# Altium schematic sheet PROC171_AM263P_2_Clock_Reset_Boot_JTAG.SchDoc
size 431 x 279 mm; Date: Not shown in title block; ApprovedBy: Not shown in title block; CheckedBy: Not shown in title block; Author: Not shown in title block; CompanyName: Not shown in title block; Engineer: Srinivas; Organization: Not shown in title block; Address1: Not shown in title block; Address2: Not shown in title block; Address3: Not shown in title block; Address4: Not shown in title block; DocumentNumber: 5; Revision: Use project parameter SCH_Rev; SheetNumber: 5; SheetTotal: 26; PageSetup: Record=PageOptions¦CenterHorizontal=True¦CenterVertical=True¦PrintScale=1.00¦XCorrection=1.00¦YCorrection=1.00¦PrintKind=0¦BorderSize=5000000¦LeftOffset=0¦BottomOffset=0¦Orientation=2¦PaperLength=1000¦PaperWidth=1000¦Scale=100¦PaperSource=15¦PrintQuality=600¦MediaType=1¦DitherType=10¦PaperKind=Letter¦PrintScaleMode=1
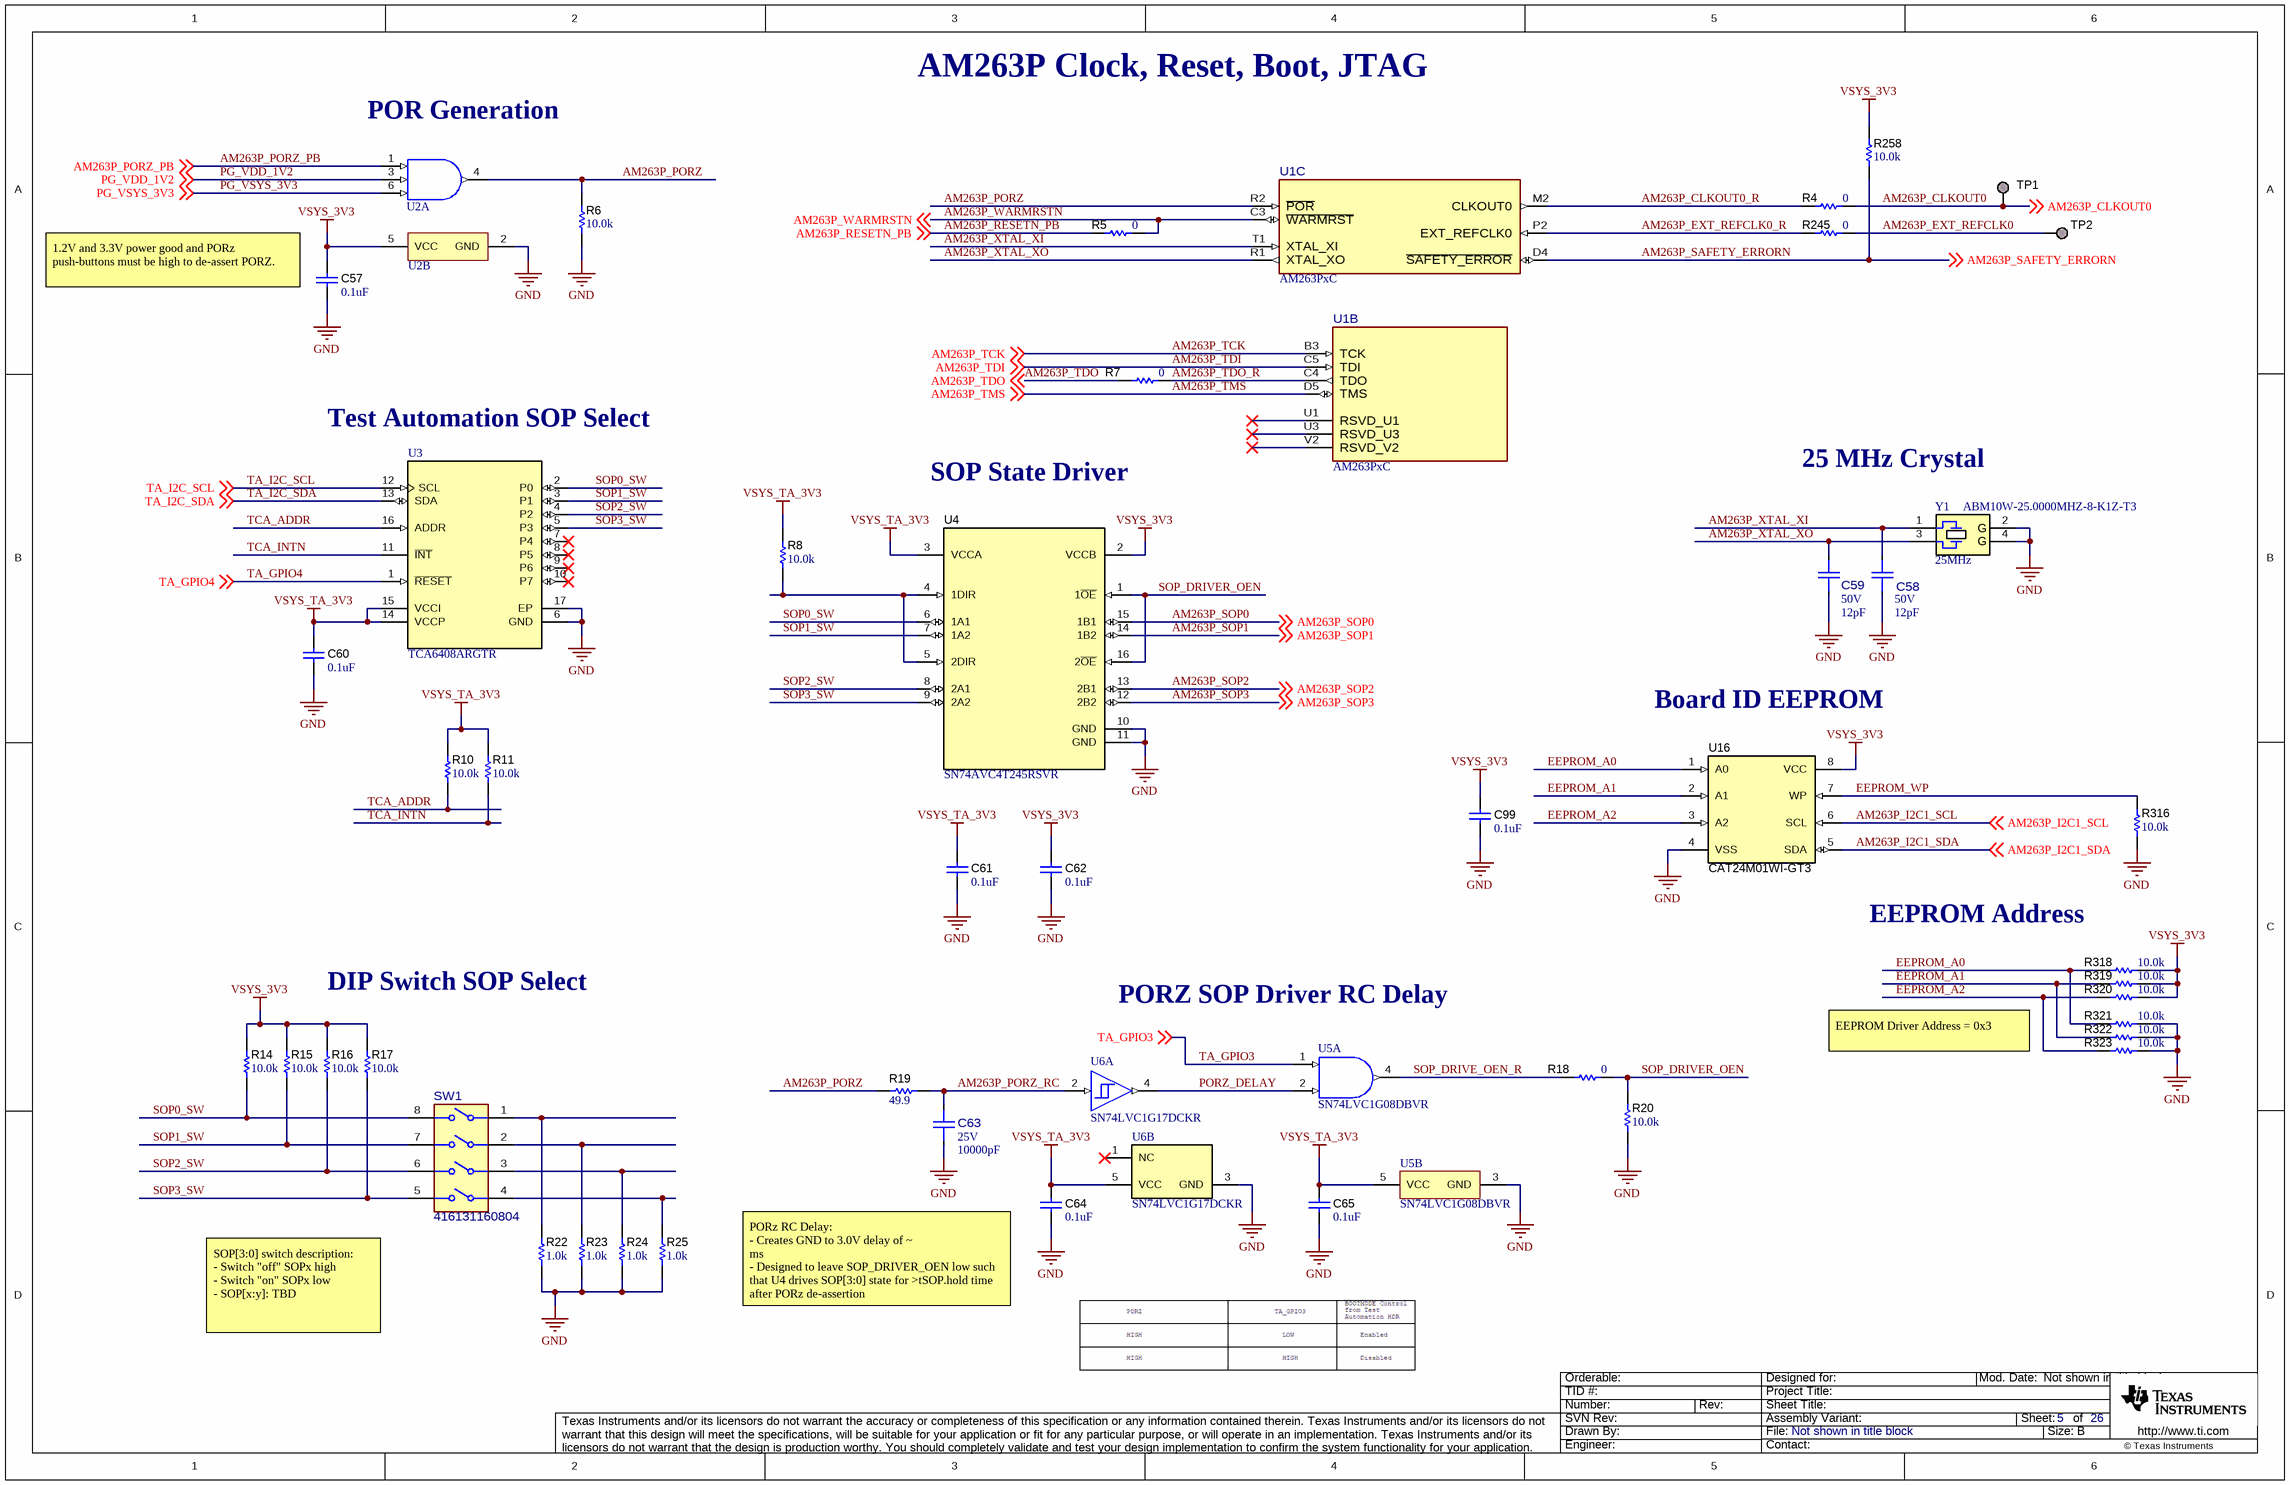
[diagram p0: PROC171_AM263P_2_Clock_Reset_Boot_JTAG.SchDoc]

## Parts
C57  ValueDisplayed: 0.1uF  [0402]  (hidden comment: GRM155R71E104KE14D)
C58  VDC_V: 50V  ValueDisplayed: 12pF  [FP-GJM1555C1H120JB01D_0402-MFG]  (hidden comment: GJM1555C1H120JB01D)
C59  VDC_V: 50V  ValueDisplayed: 12pF  [FP-GJM1555C1H120JB01D_0402-MFG]  (hidden comment: GJM1555C1H120JB01D)
C60  ValueDisplayed: 0.1uF  [0402]  (hidden comment: GRM155R71E104KE14D)
C61  ValueDisplayed: 0.1uF  [0402]  (hidden comment: GRM155R71E104KE14D)
C62  ValueDisplayed: 0.1uF  [0402]  (hidden comment: GRM155R71E104KE14D)
C63  VDC_V: 25V  ValueDisplayed: 10000pF  [FP-GRM1555C1E103JE01D_0402-MFG]  (hidden comment: GRM1555C1E103JE01D)
C64  ValueDisplayed: 0.1uF  [0402]  (hidden comment: GRM155R71E104KE14D)
C65  ValueDisplayed: 0.1uF  [0402]  (hidden comment: GRM155R71E104KE14D)
C99  ValueDisplayed: 0.1uF  [0402]  (hidden comment: GRM155R71E104KE14D)
R4  value 0  [0402L]  (hidden comment: ERJ-2GE0R00X)
R5  ValueDisplayed: 0  [0402]  (hidden comment: ERJ-2GE0R00X)
R6  ValueDisplayed: 10.0k  [0402]  (hidden comment: ERJ-2RKF1002X)
R7  value 0  [0402L]  (hidden comment: ERJ-2GE0R00X)
R8  ValueDisplayed: 10.0k  [0402]  (hidden comment: ERJ-2RKF1002X)
R10  ValueDisplayed: 10.0k  [0402]  (hidden comment: ERJ-2RKF1002X)
R11  ValueDisplayed: 10.0k  [0402]  (hidden comment: ERJ-2RKF1002X)
R14  ValueDisplayed: 10.0k  [0402]  (hidden comment: ERJ-2RKF1002X)
R15  ValueDisplayed: 10.0k  [0402]  (hidden comment: ERJ-2RKF1002X)
R16  ValueDisplayed: 10.0k  [0402]  (hidden comment: ERJ-2RKF1002X)
R17  ValueDisplayed: 10.0k  [0402]  (hidden comment: ERJ-2RKF1002X)
R18  ValueDisplayed: 0  [0402]  (hidden comment: ERJ-2GE0R00X)
R19  ValueDisplayed: 49.9  [0402]  (hidden comment: ERJ-2RKF49R9X)
R20  ValueDisplayed: 10.0k  [0402]  (hidden comment: ERJ-2RKF1002X)
R22  ValueDisplayed: 1.0k  [0402]  (hidden comment: ERJ-2GEJ102X)
R23  ValueDisplayed: 1.0k  [0402]  (hidden comment: ERJ-2GEJ102X)
R24  ValueDisplayed: 1.0k  [0402]  (hidden comment: ERJ-2GEJ102X)
R25  ValueDisplayed: 1.0k  [0402]  (hidden comment: ERJ-2GEJ102X)
R245  value 0  [0402L]  (hidden comment: ERJ-2GE0R00X)
R258  ValueDisplayed: 10.0k  [0402]  (hidden comment: ERJ-2RKF1002X)
R316  ValueDisplayed: 10.0k  [0402]  (hidden comment: ERJ-2RKF1002X)
R318  ValueDisplayed: 10.0k  [0402]  (hidden comment: ERJ-2RKF1002X)
R319  ValueDisplayed: 10.0k  [0402]  (hidden comment: ERJ-2RKF1002X)
R320  ValueDisplayed: 10.0k  [0402]  (hidden comment: ERJ-2RKF1002X)
R321  ValueDisplayed: 10.0k  [0402]  (hidden comment: ERJ-2RKF1002X)
R322  ValueDisplayed: 10.0k  [0402]  (hidden comment: ERJ-2RKF1002X)
R323  ValueDisplayed: 10.0k  [0402]  (hidden comment: ERJ-2RKF1002X)
SW1  416131160804  [FP-416131160804_SMT_SW-MFG]
TP1  TP_SM_1MM  [TP_SM_1MM]  (value not drawn)  (no BOM)
TP2  TP_SM_1MM  [TP_SM_1MM]  (value not drawn)  (no BOM)
U1  AM263PxC  [ZCZ0324A-MFG]  (parts B,C of 13)
U2  SN74LVC1G11DBVR  [DBV0006A_N]  (value not drawn)  (parts A,B of 2)
U3  TCA6408ARGTR  [RGT0016A]
U4  SN74AVC4T245RSVR  [RSV0016A]
U5  SN74LVC1G08DBVR  [DBV0005A_N]  (parts A,B of 2)
U6  SN74LVC1G17DCKR  [DCK0005A_N]  (parts A,B of 2)
U16  CAT24M01WI-GT3  [SOIC-8]
Y1  Frequency_Fixed: 25MHz  PartNumber: ABM10W-25.0000MHZ-8-K1Z-T3  [Abracon_ABM10W]  (hidden comment: ABM10W-25.0000MHZ-4-D1X-T3)

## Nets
GND: C57.1 C58.1 C59.1 C60.1 C61.1 C62.1 C63.1 C64.1 C65.1 C99.1 R6.1 R20.2 R22.1 R23.1 R24.1 R25.1 R316.2 R321.1 R322.1 R323.1 U2.2(GND) U3.6(GND) U3.17(EP) U4.10(GND) U4.11(GND) U5.3(GND) U6.3(GND) U16.4(VSS) Y1.2(GND) Y1.4(GND)
VSYS_3V3: C57.2 C62.2 C99.2 R14.1 R15.1 R16.1 R17.1 R258.2 R318.1 R319.1 R320.1 U2.5(VCC) U4.2(VCCB) U16.8(VCC)
VSYS_TA_3V3: C60.2 C61.2 C64.2 C65.2 R8.1 R10.1 R11.1 U3.14(VCCP) U3.15(VCCI) U4.3(VCCA) U5.5(VCC) U6.5(VCC)
AM263P_CLKOUT0: R4.2 TP1.1 ; off-sheet AM263P_CLKOUT0
AM263P_CLKOUT0_R: R4.1 U1.M2(CLKOUT0)
AM263P_EXT_REFCLK0: R245.2 TP2.1
AM263P_EXT_REFCLK0_R: R245.1 U1.P2(EXT_REFCLK0)
AM263P_I2C1_SCL: U16.6(SCL) ; off-sheet AM263P_I2C1_SCL
AM263P_I2C1_SDA: U16.5(SDA) ; off-sheet AM263P_I2C1_SDA
AM263P_PORZ: R6.2 R19.1 U1.R2(~{POR}) U2.4(Y)
AM263P_PORZ_PB: U2.1(A) ; off-sheet AM263P_PORZ_PB
AM263P_PORZ_RC: C63.2 R19.2 U6.2(A)
AM263P_RESETN_PB: R5.1 ; off-sheet AM263P_RESETN_PB
AM263P_SAFETY_ERRORN: R258.1 U1.D4(~{SAFETY_ERROR}) ; off-sheet AM263P_SAFETY_ERRORN
AM263P_SOP0: U4.15(1B1) ; off-sheet AM263P_SOP0
AM263P_SOP1: U4.14(1B2) ; off-sheet AM263P_SOP1
AM263P_SOP2: U4.13(2B1) ; off-sheet AM263P_SOP2
AM263P_SOP3: U4.12(2B2) ; off-sheet AM263P_SOP3
AM263P_TCK: U1.B3(TCK) ; off-sheet AM263P_TCK
AM263P_TDI: U1.C5(TDI) ; off-sheet AM263P_TDI
AM263P_TDO: R7.1 ; off-sheet AM263P_TDO
AM263P_TDO_R: R7.2 U1.C4(TDO)
AM263P_TMS: U1.D5(TMS) ; off-sheet AM263P_TMS
AM263P_WARMRSTN: R5.2 U1.C3(~{WARMRST}) ; off-sheet AM263P_WARMRSTN
AM263P_XTAL_XI: C58.2 U1.T1(XTAL_XI) Y1.1
AM263P_XTAL_XO: C59.2 U1.R1(XTAL_XO) Y1.3
EEPROM_A0: R318.2 R321.2 U16.1(A0)
EEPROM_A1: R319.2 R322.2 U16.2(A1)
EEPROM_A2: R320.2 R323.2 U16.3(A2)
EEPROM_WP: R316.1 U16.7(WP)
PG_VDD_1V2: U2.3(B) ; off-sheet PG_VDD_1V2
PG_VSYS_3V3: U2.6(C) ; off-sheet PG_VSYS_3V3
PORZ_DELAY: U5.2(B) U6.4(Y)
SOP0_SW: R14.2 SW1.8 U3.2(P0) U4.6(1A1)
SOP1_SW: R15.2 SW1.7 U3.3(P1) U4.7(1A2)
SOP2_SW: R16.2 SW1.6 U3.4(P2) U4.8(2A1)
SOP3_SW: R17.2 SW1.5 U3.5(P3) U4.9(2A2)
SOP_DRIVE_OEN_R: R18.1 U5.4(Y)
SOP_DRIVER_OEN: R18.2 R20.1 U4.1(1~{OE}) U4.16(2~{OE})
TA_GPIO3: U5.1(A) ; off-sheet TA_GPIO3
TA_GPIO4: U3.1(~{RESET}) ; off-sheet TA_GPIO4
TA_I2C_SCL: U3.12(SCL) ; off-sheet TA_I2C_SCL
TA_I2C_SDA: U3.13(SDA) ; off-sheet TA_I2C_SDA
TCA_ADDR: R10.2 U3.16(ADDR)
TCA_INTN: R11.2 U3.11(~{INT})
NetR8_2: R8.2 U4.4(1DIR) U4.5(2DIR)
NetR22_2: R22.2 SW1.1
NetR23_2: R23.2 SW1.2
NetR24_2: R24.2 SW1.3
NetR25_2: R25.2 SW1.4

Not connected (* = marked no-connect by the designer): U1 U1(RSVD_U1)* U3(RSVD_U3)* V2(RSVD_V2)*; U3 7(P4)* 8(P5)* 9(P6)* 10(P7)*; U6 1(NC)*

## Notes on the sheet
- AM263P Clock, Reset, Boot, JTAG
- (near U2) POR Generation
- (near C57) 1.2V and 3.3V power good and PORz push-buttons must be high to de-assert PORZ.
- Test Automation SOP Select
- SOP State Driver
- 25 MHz Crystal
- Board ID EEPROM
- EEPROM Address
- DIP Switch SOP Select
- PORZ SOP Driver RC Delay
- EEPROM Driver Address = 0x3
- (near C64) PORz RC Delay:
  - Creates GND to 3.0V delay of ~
  ms
  - Designed to leave SOP_DRIVER_OEN low such that U4 drives SOP[3:0] state for >tSOP.hold time after PORz de-assertion
- SOP[3:0] switch description:
  - Switch "off" SOPx high
  - Switch "on" SOPx low
  - SOP[x:y]: TBD

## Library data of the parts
C57 C60-C62 C64 C65 C99 = CMP-0006659-2: CAP, CERM, 0.1 uF, 25 V, +/- 10%, X7R, 0402; Manufacturer: MuRata; TaMin_C: -55°C; Polarized: N; SizeAreaWB_mm2: 3; U/M: EA; Value: 0.1uF; TaMax_C: 125°C; SizeZ_mm: 0.6; SizeX_mm: 1; SizeY_mm: 0.5; Value2: 25V; Cap_F: 100nF; AEC Category: Q200; Value1: Unknown
C58 C59 = CMP-0035228-1: Multi-Layer Ceramic Capacitor 12pF C0G  ±5% 0402 Paper T/R; Manufacturer: Murata; TempCo: 30ppm/°C; SizeZ_mm: 0.55mm; AEC Qualified: No
C63 = CMP-0035343-1: Chip Multilayer Ceramic Capacitors for General Purpose, 0402, 10000pF, C0G, 30ppm/°C, 5%, 25V; Manufacturer: Murata; Value: 10nF; SizeZ_mm: 0.65mm; AEC Qualified: No
R4 R7 R245 = CMP-0026992-3: RES, 0, 5%, 0.1 W, AEC-Q200 Grade 0, 0402; Manufacturer: Panasonic; Power_W: 100mW; TempCo: 600 ppm/C; Value_Code: 0000; EIA_Code: E24; SizeX_mm: 1; SizeY_mm: 0.5; SizeZ_mm: 0.6; Value2: 0.1W; AEC Qualified: Y; VDC_V: 50V; AEC Category: Q200; SizeAreaWB_mm2: 3
R5 R18 = CMP-0026992-3: RES, 0, 5%, 0.1 W, AEC-Q200 Grade 0, 0402; Manufacturer: Panasonic; Power_W: 100mW; TempCo: 600 ppm/C; Value_Code: 0000; Value: 0; EIA_Code: E24; SizeX_mm: 1; SizeY_mm: 0.5; SizeZ_mm: 0.6; Value2: 0.1W; AEC Qualified: Y; VDC_V: 50V; AEC Category: Q200; SizeAreaWB_mm2: 3
R6 R8 R10 R11 R14-R17 R20 R258 R316 R318-R323 = CMP-0026658-1: RES, 10.0 k, 1%, 0.1 W, 0402; Manufacturer: Panasonic; Power_W: 100mW; TempCo: 100 ppm/C; Value_Code: 10k0; U/M: EA; Value: 10.0k; EIA_Code: E96; Res_ohm: 10k; SizeX_mm: 1; SizeY_mm: 0.5; SizeZ_mm: 0.6; Value2: 0.1W; VDC_V: 50V; AEC Category: Q200
R19 = CMP-0026703-1: RES, 49.9, 1%, 0.1 W, AEC-Q200 Grade 0, 0402; Manufacturer: Panasonic; Power_W: 100mW; TempCo: 100 ppm/C; Value_Code: 49R9; U/M: EA; Value: 49.9; EIA_Code: E96; SizeX_mm: 1; SizeY_mm: 0.5; SizeZ_mm: 0.6; Value2: 0.1W; AEC Qualified: Y; VDC_V: 50V; AEC Grade: 0; AEC Category: Q200
R22-R25 = CMP-0078193-1: RES, 1.0 k, 5%, 0.1 W, AEC-Q200 Grade 0, 0402; Manufacturer: Panasonic; Value_Code: 1k00; SizeArea_mm2: 0.5; AEC Qualified: Y; AEC Category: Q200; Res_ohm: 1k; Value: 1.0k; SizeZ_mm: 0.6; Green_REACh: Passed; EIA_Code: E24; TempCo: 200 ppm/C; AEC Grade: 0; Power_W: 100mW; VDC_V: 50V; Value2: 0.1W; Green_Lifecycle: Active; U/M: EA; SizeX_mm: 1
SW1 = CMP-0093176-1: Dip Switch SPST 4 Position Surface Mount Slide (Standard) Actuator 25mA 24VDC; Manufacturer: Wurth; PositionCount: 4; Electromechanical Life: 1000Cycles; Circuit: 4PST; Coil Resistance_ohm: 100mΩ; VDC_V: 24V; Standoff Height: 0mm; SizeZ_mm: 2.65mm; AEC Qualified: No
TP1 TP2 = CMP-0003825-1: 1mm Test Point, SMT; Manufacturer: Any
U1 = CMP-0001698-2: Sitara™ Microcontroller; Manufacturer: Texas Instruments; SizeZ_mm: 1.4mm; Core Architecture: ARM Cortex-R5F; Data Bus Width: 32bits; Frequency_Fixed: 200MHz; Interface: I2C,SPI,UART,CAN,LIN,Ethernet,Other; Max Supply Voltage: 3.465V; Memory Size: 2MBytes; Memory Type: RAM; Min Supply Voltage: 1.14V; Number Of Cores: 1; Number Of I/Os: 140; Number Of I2C Channels: 4; Number Of Spi Channels: 5; Number Of Uart Channels: 6; Standoff Height: 0.35mm; AEC Category: Q200; CompType: IC
U2 = CMP-0051219-1: Single 3-Input Positive-AND Gate, DBV0006A, LARGE T&R; Manufacturer: Texas Instruments; Output Type: CMOS; Voltage(Nom)(V): 1.8,2.5,3.3,5; ICC @ Nom Voltage(Max)(mA): 0.01; VCC(Min)(V): 1.65; Output Drive (IOL/IOH)(Max)(mA): 32/-32; Schmitt Trigger: No; Input Type: CMOS/TTL; VCC(Max)(V): 5.5; Gate Type: AND; Rating: Catalog; tpd @ Nom Voltage(Max)(ns): 20,7.8,6.2,4.6; Bits(#): 1; F @ Nom Voltage(Max)(Mhz): 150; Logic: True; Technology Family: LVC
U3 = CMP-0043157-2: Low-Voltage 8-Bit I2C and SMBus I/O Expander, 1.65 to 5.5 V, -40 to 85 degC, 16-pin QFN (RGT), Green (RoHS & no Sb/Br); Manufacturer: Texas Instruments; # of I/Os: 8; I2C Address: 0100 00x; Reset Input: Yes; Max Frequency(kHz): 400; VCC(Max)(V): 5.5; SubFamily: I2C IO Expander; VCC(Min)(V): 1.65
U4 = CMP-0066450-2: 4-Bit Dual-Supply Bus Transceiver with Configurable Voltage-Level Shifting and 3-State Outputs, RSV0016A (UQFN-16); Alternate Manufacturer: Texas Instruments; SizeAreaWB_mm2: 10.08; SizeZ_mm: 0.55; SizeX_mm: 1.8; SizeY_mm: 2.6; SizeArea_mm2: 4.68; CompType: IC; AEC Category: Q200; AEC Qualified: N
U5 = CMP-0051588-2: Single 2-Input Positive-AND Gate, DBV0005A, LARGE T&R; Manufacturer: Texas Instruments; Logic: True; ICC @ Nom Voltage(Max)(mA): 0.01; VCC(Min)(V): 1.65; Bits(#): 1; Rating: Catalog; Schmitt Trigger: No; Voltage(Nom)(V): 1.8,2.5,3.3,5; Output Drive (IOL/IOH)(Max)(mA): 32/-32; Gate Type: AND; tpd @ Nom Voltage(Max)(ns): 4.5,6,4,5; VCC(Max)(V): 5.5; Output Type: CMOS; F @ Nom Voltage(Max)(Mhz): 150; Input Type: CMOS/TTL; Technology Family: LVC; AEC Category: Q200; AEC Qualified: N; CompType: IC
U6 = CMP-0051704-3: Single Schmitt-Trigger Buffer, DCK0005A, LARGE T&R; Manufacturer: Texas Instruments; tpd @ Nom Voltage(Max)(ns): 11,6.5,5.5,5; Bits(#): 1; VCC(Min)(V): 1.65; F @ Nom Voltage(Max)(Mhz): 150; VCC(Max)(V): 5.5; Input Type: CMOS/TTL; Sub-Family: Non-Inverting Buffer/Driver; Output Type: CMOS; Output Drive (IOL/IOH)(Max)(mA): 32/-32; 3-State Output: No; Logic: True; ICC @ Nom Voltage(Max)(mA): 0.01; Voltage(Nom)(V): 1.8,2.5,3.3,5; Rating: Catalog; Schmitt Trigger: Yes; Technology Family: LVC; AEC Category: Q200; AEC Qualified: N; CompType: IC; SizeAreaWB_mm2: 9.3; SizeArea_mm2: 4.2; SizeX_mm: 2.1; SizeY_mm: 2.0; SizeZ_mm: 1.1
U16 = CMP-0005327-2: 1024-Kb I2C CMOS Serial EEPROM, SOIC-8; Manufacturer: ON Semiconductor; SizeAreaWB_mm2: 55.131; SizeZ_mm: 1.75; SizeX_mm: 5.99; SizeY_mm: 4.9; SizeArea_mm2: 29.351
Y1 = CMP-0084811-1: Crystal, 25 MHz, 10 ppm, 4 pF, SMD; Manufacturer: Abracon Corporation; Load Capacitance: 4 pF; TaMax_C: 85°C; SizeY_mm: 2.5; SizeAreaWB_mm2: 10.5; AEC Category: Q200; Frequency Stability: 20 ppm; SizeX_mm: 2; SizeArea_mm2: 5; SizeZ_mm: 0.6; AEC Qualified: N; TaMin_C: -40°C; Frequency Tolerance: 10 ppm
